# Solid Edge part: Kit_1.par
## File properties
Sűrűség: 0,000 kg/m^3
Pontosság: 0,990
Author: bmolnar
Last saved by: bmolnar
Revision: 77
Username: bmolnar
Dokumentum tartalom típus: 0
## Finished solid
Body 1: solid body, 27 faces, 33 edges, 29 vertices, 2 separate solids.
  Faces by surface: plane 10, cylinder 8, cone 6, torus 3
  Edges by curve: circle 25, line 8
Bounding box of the edges (mm; curved faces can reach further): 22.800 x 22.200 x 3.100, from (-11.4, -11.4, 48.5) to (11.4, 10.8, 51.6).
Cylindrical faces by radius (mm): R5.24 x1, R5.7 x1, R6.92 x1, R7 x1, R8.25 x1, R10 x1, R10.8 x1, R11.4 x1
Conical faces (half-angle, radius in mm at the cone's reference point): 3 deg R6.96 x1, 14 deg R5.12 x1, 14 deg R5.3801 x1, 45 deg R5.95 x1, 45 deg R8 x1, 87 deg R5.1371 x1
Toroidal faces (ring radius, tube radius in mm): R5.6606 r0.18 x1, R6.72 r0.2 x1, R8.65 r0.4 x1
Planar faces by outward normal: +z 4, -z 4, oblique 2
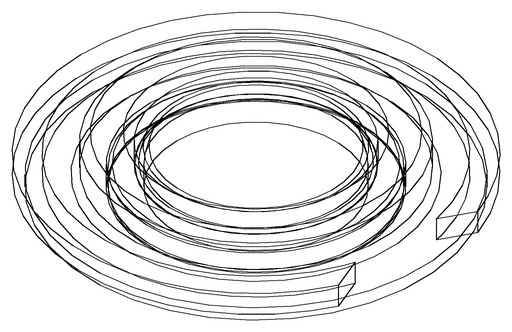
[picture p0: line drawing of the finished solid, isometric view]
